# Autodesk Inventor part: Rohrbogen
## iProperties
Created: 2006-10
Part Number: Rohrbogen
Cost Center: 6,01 kg
Document SubType Name: Modeling
Designer: grote
Authority: 6009036,9 mm^3
Manufacturer: Standard
Standards Organization: Custom
Masse: 0,000 kg
Flaeche: 000,0E+0mm^2
Volumen: 000,0E+0mm^3
SaveDate: 2006-10-11
SaveTime: 08:21
FileName: Rohrbogen
TotalMass: 6,01 kg
TotalVolume: 6009036,9 mm^3
Author: grote
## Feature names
1. Runde Anordnung1 [Circular Pattern]
2. Sweeping1
3. Trennen1
